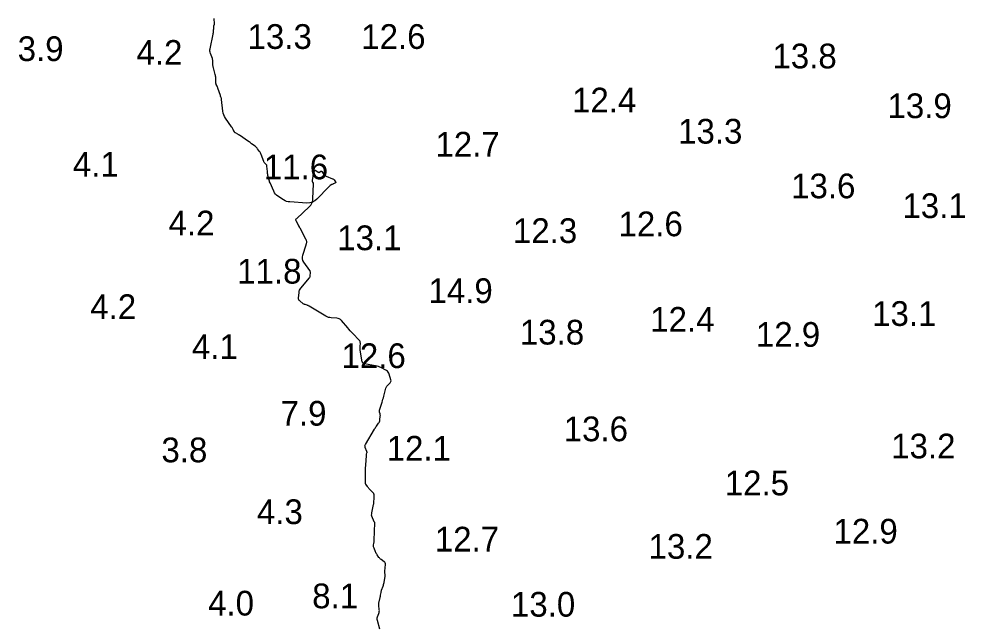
# Model space of a CAD drawing. Extents: x 815352 to 820877, y 582403 to 597439.
# Drawn here: x 820167.5 to 820359, y 591695.4 to 591817.4 of the extents above; entities that cross this region are included whole.
import ezdxf

# ---------------------------------------------------------------- set-up
doc = ezdxf.new("R2010")
doc.units = 0
doc.layers.add('V-CONT-EL12', color=7, linetype='Continuous')
doc.layers.add('V-TOPO-SOUN', color=7, linetype='Continuous')

msp = doc.modelspace()

# ---------------------------------------------------------------- linework, layer by layer
at = {"layer": 'V-CONT-EL12'}
msp.add_lwpolyline([(820240.54, 591694.01), (820240.04, 591695.74), (820240, 591695.93), (820239.99, 591696.11), (820240.01, 591696.29), (820240.06, 591696.47), (820240.33, 591697.18), (820240.39, 591697.36), (820240.42, 591697.55), (820240.43, 591697.73), (820240.42, 591697.92), (820240.33, 591698.82), (820240.32, 591699), (820240.32, 591699.18), (820240.34, 591699.36), (820240.38, 591699.54), (820240.58, 591700.36), (820240.61, 591700.49), (820240.64, 591700.61), (820240.67, 591700.74), (820240.69, 591700.86), (820240.77, 591701.37), (820240.8, 591701.49), (820240.83, 591701.62), (820240.86, 591701.74), (820240.9, 591701.86), (820241.19, 591702.68), (820241.24, 591702.86), (820241.3, 591703.04), (820241.34, 591703.22), (820241.38, 591703.4), (820241.62, 591704.7), (820241.63, 591704.79), (820241.63, 591704.87), (820241.63, 591704.96), (820241.62, 591705.04), (820241.57, 591705.38), (820241.56, 591705.47), (820241.55, 591705.55), (820241.55, 591705.64), (820241.55, 591705.72), (820241.67, 591707.06), (820241.67, 591707.23), (820241.62, 591707.38), (820241.54, 591707.51), (820241.41, 591707.62), (820240.8, 591708.05), (820240.67, 591708.15), (820240.55, 591708.26), (820240.44, 591708.38), (820240.35, 591708.51), (820239.98, 591709.05), (820239.89, 591709.18), (820239.8, 591709.32), (820239.73, 591709.47), (820239.66, 591709.62), (820239.35, 591710.35), (820239.31, 591710.48), (820239.28, 591710.61), (820239.27, 591710.74), (820239.28, 591710.88), (820239.34, 591711.43), (820239.35, 591711.56), (820239.37, 591711.7), (820239.38, 591711.84), (820239.38, 591711.97), (820239.54, 591715.49), (820239.54, 591715.51), (820239.53, 591715.53), (820239.53, 591715.55), (820239.51, 591715.57), (820239.46, 591715.63), (820239.44, 591715.65), (820239.43, 591715.67), (820239.42, 591715.69), (820239.41, 591715.71), (820238.9, 591716.84), (820238.88, 591716.89), (820238.87, 591716.95), (820238.86, 591717), (820238.87, 591717.06), (820238.89, 591717.28), (820238.9, 591717.33), (820238.91, 591717.39), (820238.92, 591717.44), (820238.93, 591717.5), (820239.28, 591719.19), (820239.3, 591719.33), (820239.32, 591719.47), (820239.33, 591719.61), (820239.34, 591719.76), (820239.36, 591720.44), (820239.37, 591720.53), (820239.37, 591720.62), (820239.37, 591720.71), (820239.37, 591720.8), (820239.37, 591721.16), (820239.36, 591721.24), (820239.34, 591721.32), (820239.3, 591721.4), (820239.25, 591721.47), (820238.33, 591722.45), (820238.25, 591722.54), (820238.18, 591722.63), (820238.1, 591722.72), (820238.03, 591722.82), (820237.68, 591723.34), (820237.66, 591723.38), (820237.64, 591723.42), (820237.63, 591723.46), (820237.63, 591723.5), (820237.63, 591723.67), (820237.63, 591723.72), (820237.63, 591723.76), (820237.63, 591723.8), (820237.63, 591723.84), (820237.61, 591726.64), (820237.62, 591726.68), (820237.62, 591726.72), (820237.63, 591726.76), (820237.64, 591726.81), (820237.7, 591726.97), (820237.71, 591727.01), (820237.72, 591727.06), (820237.73, 591727.1), (820237.73, 591727.14), (820237.82, 591729.14), (820237.83, 591729.21), (820237.84, 591729.28), (820237.85, 591729.34), (820237.86, 591729.41), (820237.93, 591729.67), (820237.94, 591729.74), (820237.94, 591729.8), (820237.93, 591729.87), (820237.91, 591729.93), (820237.58, 591730.75), (820237.53, 591730.91), (820237.52, 591731.07), (820237.55, 591731.22), (820237.62, 591731.37), (820239.44, 591734.41), (820239.54, 591734.57), (820239.64, 591734.73), (820239.74, 591734.88), (820239.85, 591735.03), (820240.29, 591735.64), (820240.38, 591735.79), (820240.45, 591735.94), (820240.5, 591736.1), (820240.53, 591736.27), (820240.63, 591737.11), (820240.64, 591737.21), (820240.63, 591737.31), (820240.62, 591737.41), (820240.6, 591737.51), (820240.48, 591737.9), (820240.46, 591737.99), (820240.45, 591738.09), (820240.46, 591738.19), (820240.48, 591738.29), (820240.98, 591739.89), (820241.07, 591740.19), (820241.16, 591740.49), (820241.25, 591740.79), (820241.33, 591741.09), (820241.74, 591742.71), (820241.79, 591742.88), (820241.87, 591743.03), (820241.97, 591743.17), (820242.09, 591743.3), (820242.61, 591743.8), (820242.72, 591743.93), (820242.78, 591744.07), (820242.8, 591744.23), (820242.77, 591744.4), (820242.45, 591745.56), (820242.36, 591745.8), (820242.23, 591746), (820242.06, 591746.18), (820241.85, 591746.31), (820240.76, 591746.89), (820240.5, 591747.01), (820240.24, 591747.12), (820239.96, 591747.2), (820239.68, 591747.26), (820237.43, 591747.65), (820237.38, 591747.66), (820237.33, 591747.68), (820237.29, 591747.7), (820237.24, 591747.73), (820237.08, 591747.86), (820237.04, 591747.9), (820237.01, 591747.94), (820236.99, 591747.99), (820236.98, 591748.04), (820236.57, 591750.45), (820236.55, 591750.63), (820236.53, 591750.8), (820236.53, 591750.97), (820236.54, 591751.14), (820236.59, 591751.83), (820236.58, 591752), (820236.54, 591752.15), (820236.47, 591752.3), (820236.37, 591752.43), (820235.04, 591753.81), (820234.77, 591754.08), (820234.52, 591754.36), (820234.27, 591754.64), (820234.02, 591754.93), (820232.74, 591756.44), (820232.54, 591756.63), (820232.32, 591756.77), (820232.08, 591756.86), (820231.8, 591756.9), (820230.67, 591756.97), (820230.4, 591757), (820230.13, 591757.06), (820229.87, 591757.16), (820229.62, 591757.29), (820226.21, 591759.34), (820226.12, 591759.4), (820226.02, 591759.44), (820225.92, 591759.48), (820225.82, 591759.51), (820225.41, 591759.63), (820225.31, 591759.67), (820225.21, 591759.71), (820225.12, 591759.76), (820225.03, 591759.82), (820224.34, 591760.37), (820224.21, 591760.49), (820224.13, 591760.62), (820224.09, 591760.78), (820224.08, 591760.95), (820224.18, 591762.09), (820224.22, 591762.34), (820224.29, 591762.57), (820224.4, 591762.78), (820224.55, 591762.98), (820226.27, 591765.06), (820226.35, 591765.17), (820226.41, 591765.29), (820226.44, 591765.41), (820226.46, 591765.54), (820226.49, 591766.08), (820226.49, 591766.21), (820226.46, 591766.34), (820226.41, 591766.46), (820226.35, 591766.57), (820225.16, 591768.24), (820224.97, 591768.56), (820224.88, 591768.9), (820224.86, 591769.25), (820224.94, 591769.61), (820225.59, 591771.7), (820225.61, 591771.76), (820225.63, 591771.82), (820225.65, 591771.89), (820225.67, 591771.95), (820225.74, 591772.25), (820225.75, 591772.29), (820225.76, 591772.33), (820225.75, 591772.37), (820225.74, 591772.41), (820225.7, 591772.57), (820225.69, 591772.61), (820225.68, 591772.65), (820225.66, 591772.69), (820225.64, 591772.73), (820224.39, 591775.07), (820224.36, 591775.14), (820224.32, 591775.2), (820224.29, 591775.27), (820224.25, 591775.34), (820224.11, 591775.6), (820224.08, 591775.67), (820224.04, 591775.74), (820224.01, 591775.8), (820223.97, 591775.87), (820223.61, 591776.58), (820223.56, 591776.72), (820223.56, 591776.85), (820223.61, 591776.97), (820223.7, 591777.08), (820226.22, 591779.42), (820226.55, 591779.78), (820226.79, 591780.18), (820226.94, 591780.62), (820227, 591781.11), (820227.13, 591784.02), (820227.13, 591784.07), (820227.12, 591784.12), (820227.11, 591784.17), (820227.08, 591784.22), (820226.97, 591784.41), (820226.95, 591784.46), (820226.93, 591784.51), (820226.93, 591784.56), (820226.93, 591784.62), (820226.99, 591785.37), (820227.01, 591785.51), (820227.03, 591785.66), (820227.06, 591785.8), (820227.09, 591785.94), (820227.29, 591786.69), (820227.33, 591786.79), (820227.39, 591786.84), (820227.47, 591786.83), (820227.56, 591786.78), (820228.03, 591786.43), (820228.09, 591786.4), (820228.16, 591786.38), (820228.23, 591786.39), (820228.3, 591786.43), (820228.58, 591786.61), (820228.65, 591786.64), (820228.71, 591786.64), (820228.77, 591786.61), (820228.82, 591786.56), (820229.22, 591785.95), (820229.31, 591785.83), (820229.42, 591785.74), (820229.54, 591785.66), (820229.67, 591785.59), (820230.92, 591785.1), (820231.02, 591785.06), (820231.12, 591785), (820231.2, 591784.93), (820231.28, 591784.85), (820231.58, 591784.51), (820231.63, 591784.43), (820231.64, 591784.37), (820231.61, 591784.32), (820231.53, 591784.27), (820231.16, 591784.1), (820231.07, 591784.06), (820230.99, 591784.01), (820230.91, 591783.97), (820230.82, 591783.92), (820230.5, 591783.72), (820230.43, 591783.67), (820230.35, 591783.61), (820230.28, 591783.55), (820230.21, 591783.48), (820227.81, 591780.98), (820227.36, 591780.6), (820226.87, 591780.34), (820226.33, 591780.2), (820225.74, 591780.18), (820222.32, 591780.4), (820221.98, 591780.44), (820221.66, 591780.53), (820221.35, 591780.65), (820221.05, 591780.82), (820219.9, 591781.57), (820219.63, 591781.77), (820219.4, 591782), (820219.2, 591782.27), (820219.05, 591782.57), (820218.31, 591784.27), (820218.23, 591784.45), (820218.17, 591784.63), (820218.11, 591784.82), (820218.06, 591785.01), (820217.88, 591785.77), (820217.84, 591785.96), (820217.81, 591786.15), (820217.78, 591786.35), (820217.76, 591786.54), (820217.68, 591787.67), (820217.67, 591787.76), (820217.63, 591787.85), (820217.59, 591787.93), (820217.52, 591788), (820217.23, 591788.27), (820217.16, 591788.34), (820217.11, 591788.41), (820217.06, 591788.5), (820217.02, 591788.59), (820216.52, 591789.99), (820216.46, 591790.15), (820216.38, 591790.31), (820216.3, 591790.46), (820216.2, 591790.6), (820215.78, 591791.17), (820215.68, 591791.3), (820215.56, 591791.43), (820215.43, 591791.55), (820215.3, 591791.66), (820214.58, 591792.18), (820214.42, 591792.3), (820214.25, 591792.42), (820214.08, 591792.54), (820213.92, 591792.66), (820212.15, 591793.89), (820212.05, 591793.95), (820211.96, 591794.01), (820211.86, 591794.07), (820211.76, 591794.12), (820211.29, 591794.38), (820211.23, 591794.42), (820211.18, 591794.46), (820211.13, 591794.51), (820211.1, 591794.56), (820210.95, 591794.8), (820210.92, 591794.86), (820210.89, 591794.92), (820210.85, 591794.98), (820210.82, 591795.04), (820210.68, 591795.33), (820210.65, 591795.4), (820210.61, 591795.47), (820210.57, 591795.53), (820210.53, 591795.6), (820209.28, 591797.36), (820209.08, 591797.68), (820208.92, 591798.02), (820208.81, 591798.37), (820208.75, 591798.75), (820208.49, 591801.1), (820208.48, 591801.14), (820208.48, 591801.17), (820208.48, 591801.2), (820208.47, 591801.23), (820208.46, 591801.35), (820208.46, 591801.39), (820208.45, 591801.42), (820208.44, 591801.45), (820208.43, 591801.47), (820208.32, 591801.71), (820208.3, 591801.76), (820208.28, 591801.81), (820208.26, 591801.86), (820208.25, 591801.91), (820207.76, 591803.4), (820207.73, 591803.51), (820207.69, 591803.61), (820207.65, 591803.71), (820207.6, 591803.8), (820207.42, 591804.2), (820207.39, 591804.3), (820207.36, 591804.4), (820207.34, 591804.5), (820207.33, 591804.61), (820207.33, 591805.46), (820207.32, 591805.64), (820207.3, 591805.82), (820207.27, 591805.99), (820207.23, 591806.16), (820206.84, 591807.55), (820206.8, 591807.7), (820206.78, 591807.85), (820206.76, 591808.01), (820206.75, 591808.16), (820206.75, 591808.79), (820206.74, 591808.95), (820206.72, 591809.1), (820206.68, 591809.25), (820206.64, 591809.4), (820206.23, 591810.46), (820206.16, 591810.69), (820206.13, 591810.92), (820206.13, 591811.15), (820206.16, 591811.38), (820206.78, 591814.35), (820206.8, 591814.45), (820206.81, 591814.55), (820206.83, 591814.65), (820206.84, 591814.75), (820206.88, 591815.17), (820206.89, 591815.27), (820206.9, 591815.36), (820206.91, 591815.45), (820206.91, 591815.55), (820206.94, 591816.02), (820206.95, 591816.06), (820206.96, 591816.11), (820206.97, 591816.16), (820206.98, 591816.2), (820207.05, 591816.38), (820207.07, 591816.43), (820207.07, 591816.48), (820207.08, 591816.52), (820207.08, 591816.57), (820206.99, 591817.39), (820206.98, 591817.55)], dxfattribs=at)

# ---------------------------------------------------------------- texts
at = {"layer": 'V-TOPO-SOUN'}
for s, p in [('13.3 ', (820213.76, 591811.37)), ('12.6 ', (820236.77, 591811.37)), ('3.9', (820167.22, 591808.91)), ('4.2', (820191.27, 591808.15)), ('13.8 ', (820320, 591807.43)), ('12.4 ', (820279.44, 591798.51)), ('13.9 ', (820343.29, 591797.36)), ('13.3 ', (820300.9, 591792.21)), ('12.7 ', (820251.79, 591789.58)), ('4.1', (820178.38, 591785.51)), ('11.6 ', (820217.05, 591784.99)), ('13.6 ', (820323.78, 591781.15)), ('13.1 ', (820346.31, 591777.15)), ('4.2', (820197.77, 591773.64)), ('12.6 ', (820288.84, 591773.47)), ('12.3 ', (820267.47, 591772.1)), ('13.1 ', (820231.91, 591770.65)), ('11.8 ', (820211.66, 591763.89)), ('14.9 ', (820250.38, 591759.96)), ('4.2', (820181.92, 591756.71)), ('12.4 ', (820295.26, 591754.15)), ('13.1 ', (820340.18, 591755.33)), ('13.8 ', (820268.88, 591751.56)), ('12.9 ', (820316.65, 591751.1)), ('4.1', (820202.5, 591748.64)), ('12.6 ', (820232.77, 591746.8)), ('7.9', (820220.44, 591735.15)), ('13.6 ', (820277.75, 591732)), ('3.8', (820196.32, 591727.74)), ('12.1 ', (820241.92, 591728.07)), ('13.2 ', (820344.04, 591728.53)), ('12.5 ', (820310.35, 591721.05)), ('4.3', (820215.65, 591715.24)), ('12.9 ', (820332.36, 591711.3)), ('12.7 ', (820251.66, 591709.69)), ('13.2 ', (820294.93, 591708.22)), ('4.0', (820205.77, 591696.74)), ('8.1', (820226.84, 591698.21)), ('13.0 ', (820267.07, 591696.51))]:
    msp.add_text(s, height=5, dxfattribs=at).set_placement(p)

doc.saveas('drawing.dxf')
